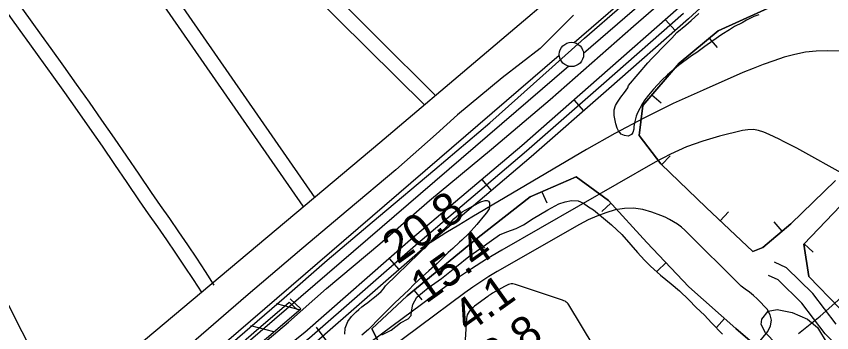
# Model space of a CAD drawing. Extents: x 3625074 to 3663148, y 511451 to 537151.
# Drawn here: x 3641799 to 3643476, y 523293 to 523944 of the extents above; entities that cross this region are included whole.
import ezdxf

# ---------------------------------------------------------------- set-up
doc = ezdxf.new("R2010")
doc.units = 0
for name, color, linetype in [('V-BORW-LINE', 7, 'Continuous'), ('V-FLOD-BASE', 7, 'Continuous'), ('V-LEVE-TOET', 7, 'Continuous'), ('V-RIVR-RANG', 7, 'Continuous'), ('V-ROAD-CNTR', 7, 'Continuous'), ('V-RRAP-FSHR', 7, 'Continuous'), ('V-SITE-VEGE', 7, 'Continuous'), ('V-SURV-LINE', 7, 'Continuous'), ('V-TOPO-DPTH', 7, 'Continuous'), ('V-TOPO-MINR', 7, 'Continuous'), ('V-TOPO-SHOR', 7, 'Continuous')]:
    doc.layers.add(name, color=color, linetype=linetype)

msp = doc.modelspace()

# ---------------------------------------------------------------- linework, layer by layer
at = {"layer": 'V-BORW-LINE'}
for p, q in [((3643224.4, 523898.9), (3643240.4, 523879.7)), ((3643106.3, 523782.3), (3643125.2, 523766)), ((3643126.5, 523638.8), (3643143.9, 523656.9)), ((3642880.2, 523583.2), (3642890.2, 523560.3)), ((3643022, 523559.4), (3643003.6, 523542.5)), ((3643246.8, 523523.6), (3643264, 523541.7)), ((3643374.1, 523502.3), (3643358, 523521.3)), ((3642745.8, 523486.1), (3642761.7, 523466.8)), ((3643419.6, 523476.2), (3643437.7, 523458.9)), ((3643135.4, 523437.3), (3643117.3, 523420)), ((3642617.1, 523380.3), (3642633, 523361)), ((3643255.8, 523322.3), (3643239.1, 523303.7))]:
    msp.add_line(p, q, dxfattribs=at)
for points in [[(3643484, 523606.3), (3643392, 523517.4), (3643334.4, 523468.5), (3643313.8, 523460.2), (3643218, 523550.8), (3643124.7, 523640.6), (3643080.3, 523698.5), (3643087.7, 523760.7), (3643162.2, 523847.3), (3643242.7, 523914.1), (3643381.8, 523977.8), (3643447.3, 523989.3), (3643529.5, 523993.4)], [(3643529.5, 523993.4), (3643447.3, 523989.3), (3643381.8, 523977.8), (3643242.7, 523914.1), (3643162.2, 523847.3), (3643087.7, 523760.7), (3643080.3, 523698.5), (3643124.7, 523640.6), (3643218, 523550.8), (3643313.8, 523460.2), (3643334.4, 523468.5), (3643392, 523517.4), (3643484, 523606.3)], [(3643375, 523158.9), (3643273.5, 523101.1), (3643205.5, 523058.5), (3643146.1, 523014.8), (3643079, 522959.4), (3643024.6, 522924.2), (3642958.5, 522908.3), (3642875.7, 522934.7), (3642769.3, 523010.4), (3642676.7, 523100.7), (3642574.7, 523212.8), (3642530.5, 523301.4), (3642603.3, 523368.9), (3642749, 523488.7), (3642856, 523572.7), (3642950.3, 523613.8), (3643016.9, 523565), (3643096.1, 523478.5), (3643182.6, 523387.8), (3643278.9, 523301.7), (3643371.1, 523222.8), (3643404.9, 523181.4), (3643398.8, 523171.9), (3643370.1, 523156.1)], [(3643370.1, 523156.1), (3643398.8, 523171.9), (3643404.9, 523181.4), (3643371.1, 523222.8), (3643278.9, 523301.7), (3643182.6, 523387.8), (3643096.1, 523478.5), (3643016.9, 523565), (3642950.3, 523613.8), (3642856, 523572.7), (3642749, 523488.7), (3642603.3, 523368.9), (3642530.5, 523301.4), (3642574.7, 523212.8), (3642676.7, 523100.7), (3642769.3, 523010.4), (3642875.7, 522934.7), (3642958.5, 522908.3), (3643024.6, 522924.2), (3643079, 522959.4), (3643146.1, 523014.8), (3643205.5, 523058.5), (3643273.5, 523101.1), (3643375, 523158.9)], [(3643491.5, 523344.1), (3643429.3, 523409), (3643418.7, 523475.3), (3643494.2, 523554.1)], [(3643494.2, 523554.1), (3643418.7, 523475.3), (3643429.3, 523409), (3643491.5, 523344.1)]]:
    msp.add_lwpolyline(points, dxfattribs=at)
at = {"layer": 'V-FLOD-BASE'}
msp.add_lwpolyline([(3640084.7, 521422.5), (3640206.5, 521525.7), (3640349.2, 521649.5), (3640530.1, 521801.4), (3640700.2, 521944.7), (3640815.3, 522042.4), (3640935.5, 522146.4), (3641004.7, 522203.9), (3641096.4, 522280.2), (3641207.3, 522373.9), (3641292.3, 522443.2), (3641395, 522533), (3641502.5, 522624.4), (3641618.4, 522721.2), (3641693.6, 522786.7), (3641777.8, 522856.7), (3641876.2, 522941), (3641962.2, 523015.9), (3642078.1, 523113.5), (3642175.7, 523196.2), (3642287.5, 523294), (3642360.1, 523356.2), (3642377.5, 523340.3)], dxfattribs=at)
at = {"layer": 'V-LEVE-TOET'}
for points in [[(3641773.7, 522787.8), (3641839.9, 522855.8), (3641920.2, 522930.4), (3641999.6, 523001.6), (3642112.5, 523101.3), (3642236.2, 523211.8), (3642358.8, 523315.2), (3642437.1, 523384.5), (3642546.6, 523476.2), (3642648.7, 523564.9), (3642776.2, 523670.5), (3642897.2, 523773.1), (3643068.6, 523923.3), (3643211.9, 524048.6), (3643296.8, 524120.9), (3643330.7, 524156.9), (3643348, 524170.9), (3643379.3, 524190.1), (3643409.3, 524208.5), (3643430.4, 524223.5), (3643456, 524241.7), (3643472.5, 524256.5), (3643504.8, 524290.1)], [(3642945.3, 523946.4), (3642876.6, 523877.7), (3642798.6, 523817.2), (3642706.5, 523741.1), (3642662.7, 523701.4), (3642579.5, 523628.2), (3642481.6, 523545.8), (3642386.1, 523465.8), (3642270.9, 523367.8), (3642158.8, 523270.6), (3642018.1, 523150.9), (3641911.7, 523056.7), (3641792.6, 522962)]]:
    msp.add_lwpolyline(points, dxfattribs=at)
at = {"layer": 'V-ROAD-CNTR'}
for p, q in [((3643153.9, 523914.3), (3643134.1, 523936.8)), ((3642966, 523749.3), (3642946.2, 523771.9)), ((3642776.7, 523585.7), (3642757.3, 523608.6)), ((3642586.7, 523423.5), (3642566.9, 523446.1))]:
    msp.add_line(p, q, dxfattribs=at)
for points in [[(3641531.3, 522821.3), (3641851.4, 523101.1), (3642546.6, 523684.6), (3643178.2, 524219.8), (3643515, 524516.6), (3644577.1, 525427.6), (3644649.7, 525493.9)], [(3641481.6, 524913.4), (3642413.1, 523570.8)], [(3641759.4, 522860.1), (3641937.2, 523010.9), (3642077.2, 523130.7), (3642213.8, 523247.3), (3642349.7, 523364.8), (3642438.7, 523442.6), (3642544.1, 523531.2), (3642660.1, 523629.1), (3642772.9, 523724.7), (3642901.5, 523839.2), (3642967.5, 523899.2), (3643044.9, 523966.1), (3643170.8, 524070.2), (3643269.5, 524151.7), (3643357.5, 524224.7), (3643379, 524244.2), (3643390, 524254), (3643408.6, 524270.7), (3643449.8, 524305.7), (3643542.1, 524386.6)], [(3641981, 524140.9), (3642388.4, 523553.7)], [(3643376.5, 524137.1), (3643310.1, 524056.4), (3643181.5, 523938.5), (3643017.7, 523794.7), (3642858.3, 523654.8), (3642629.7, 523461.2), (3642412, 523270.7), (3642307.5, 523187.5), (3642202.2, 523096.9), (3642137.4, 523040.9), (3642086.8, 522990.9), (3642054.2, 522948.8), (3642038.4, 522910.8), (3642039, 522889), (3642040.9, 522865), (3642051.8, 522825.6), (3642068.8, 522782.8), (3642084.3, 522721.3), (3642106.6, 522661.5), (3642134.3, 522618), (3642159.8, 522585), (3642187.5, 522517.2), (3642202.2, 522460.1), (3642207.9, 522380)], [(3642660.2, 523782.6), (3642422.8, 524018.5)], [(3642206.2, 523391.3), (3642188.3, 523418.9), (3642170.2, 523446.4), (3642151.9, 523473.8), (3642133.4, 523501), (3642114.7, 523528.1), (3642095.8, 523555.1), (3642076.8, 523581.8), (3642051.7, 523619), (3642026.4, 523656.3), (3642000.8, 523693.5), (3641975.1, 523730.6), (3641949.3, 523767.6), (3641923.2, 523804.4), (3641897, 523841.2), (3641870.7, 523877.8), (3641851, 523904.7), (3641831.6, 523931.7), (3641812.4, 523958.8), (3641781.7, 524003)], [(3642181.1, 523375), (3642163.2, 523402.5), (3642145.2, 523429.8), (3642127, 523457), (3642108.6, 523484.1), (3642090, 523511), (3642071.3, 523537.8), (3642052.2, 523564.7), (3642026.9, 523602.2), (3642001.6, 523639.4), (3641976.1, 523676.5), (3641950.5, 523713.5), (3641924.7, 523750.3), (3641898.8, 523787.1), (3641872.7, 523823.7), (3641846.4, 523860.2), (3641826.7, 523887.1), (3641807.2, 523914.3), (3641787.9, 523941.6), (3641756.9, 523986.1)], [(3642639.1, 523761.3), (3642401.7, 523997.2)], [(3643161.5, 523960.9), (3642997.9, 523817.2), (3642838.7, 523677.5), (3642610.1, 523483.9), (3642392.8, 523293.7), (3642288.4, 523210.6), (3642182.6, 523119.6), (3642117.1, 523063), (3642064.3, 523010.9), (3642028, 522964), (3642008.3, 522916.5), (3642009, 522887.4), (3642011.3, 522859.7), (3642023.3, 522816.1), (3642040.2, 522773.5), (3642055.6, 522712.3), (3642079.6, 522648.1), (3642109.8, 522600.8), (3642133.6, 522569.9), (3642159, 522507.7), (3642172.4, 522455.3), (3642176.7, 522394.7)], [(3643171.5, 523949.7), (3643007.8, 523805.9), (3642848.5, 523666.2), (3642619.9, 523472.6), (3642402.4, 523282.2), (3642298, 523199.1), (3642192.4, 523108.3), (3642127.3, 523052), (3642075.5, 523000.9), (3642041.1, 522956.4), (3642023.4, 522913.6), (3642024, 522888.2), (3642026.1, 522862.3), (3642037.5, 522820.9), (3642054.5, 522778.1), (3642070, 522716.8), (3642093.1, 522654.8), (3642122, 522609.4), (3642146.7, 522577.4), (3642173.3, 522512.4), (3642187.3, 522457.7), (3642193.4, 522371.6)], [(3641533.4, 523841), (3641893.6, 523132.1)], [(3643485, 523311), (3643437.2, 523373.6), (3643383.2, 523426.9), (3643358.6, 523438.2)], [(3643517.3, 523237), (3643462.4, 523291.1), (3643414.6, 523353.7), (3643365.9, 523401.8), (3643346.1, 523410.9)], [(3642415.6, 523304.8), (3642443.4, 523267.9), (3642466.5, 523241.1), (3642485.7, 523217.2), (3642519.6, 523179.9), (3642562.5, 523130.5), (3642612, 523072.4), (3642677.6, 523002.7), (3642726.4, 522957.6), (3642774, 522925.7), (3642830.3, 522901.3), (3642884.4, 522883.9), (3642942.1, 522880.4), (3642983.3, 522886.7), (3643078.4, 522923.2), (3643173, 522979.4), (3643261.4, 523030.7), (3643325.6, 523069.4), (3643362.4, 523096.7), (3643389.7, 523114.2), (3643407.6, 523140.2), (3643411.9, 523159.7)]]:
    msp.add_lwpolyline(points, dxfattribs=at)
at = {"layer": 'V-RRAP-FSHR'}
for p, q in [((3642381.7, 523340.6), (3642334.4, 523352.9)), ((3642328.4, 523295.2), (3642281.1, 523307.4))]:
    msp.add_line(p, q, dxfattribs=at)
msp.add_lwpolyline([(3641583.2, 522658.8), (3642384.1, 523342.7), (3642362.2, 523362.9)], dxfattribs=at)
at = {"layer": 'V-SITE-VEGE'}
for points in [[(3643326.4, 523947), (3643316.1, 523943.3), (3643301.2, 523935.9), (3643291.9, 523930.6), (3643276.3, 523922.6), (3643265.7, 523916.3), (3643250, 523906.3), (3643243.4, 523901.9), (3643215, 523881.5), (3643198.7, 523869.5), (3643187.7, 523862.3), (3643161, 523842.8), (3643138.5, 523823.5), (3643127.1, 523812.7), (3643109.9, 523794.3), (3643099.1, 523781.5), (3643092, 523772.2), (3643086.8, 523764.8), (3643076.8, 523745.2), (3643074.3, 523738.7), (3643071.8, 523730.3), (3643070.7, 523724.8), (3643069.5, 523717), (3643069, 523711.7), (3643066.8, 523704.9), (3643064.4, 523700.8), (3643057.5, 523697.7), (3643049.7, 523698.6), (3643043.2, 523701.4), (3643037.8, 523708.1), (3643035.1, 523713.7), (3643032, 523722.9), (3643030.6, 523729.8), (3643028.9, 523740), (3643028.8, 523746.6), (3643028.9, 523751.8), (3643031.8, 523760.5), (3643035.9, 523767.3), (3643042.4, 523777.5), (3643049.9, 523787.1), (3643057, 523796.7), (3643058.5, 523801.3), (3643098, 523847.9), (3643106.1, 523857.1), (3643114.9, 523865.7), (3643127.7, 523878.7), (3643147.2, 523899.1), (3643157.7, 523910.2), (3643176.1, 523925.4), (3643187.1, 523935.2), (3643203.2, 523949.8)], [(3642474.6, 523290.6), (3642475.6, 523302.4), (3642478, 523309.2), (3642480.9, 523316.3), (3642488.7, 523326.8), (3642497.8, 523336.4), (3642503.8, 523341.1), (3642509.8, 523346.2), (3642515.5, 523350.6), (3642522.2, 523355.3), (3642526.2, 523358.5), (3642533.2, 523364.5), (3642539.2, 523369.2), (3642549.3, 523377.7), (3642554.4, 523383.8), (3642558.4, 523389.6), (3642627.4, 523456.9), (3642636.4, 523465.5), (3642639.8, 523468), (3642647.8, 523476.3), (3642652.5, 523480.7), (3642658.6, 523488.4), (3642663.4, 523493.5), (3642673.1, 523501.4), (3642680.4, 523507.7), (3642691.9, 523519.5), (3642699, 523527.1), (3642709, 523536.3), (3642716.1, 523541.7), (3642738.6, 523554.4), (3642754.6, 523562.5), (3642763.5, 523564.8), (3642767.7, 523565.4), (3642770.3, 523563.7), (3642772.1, 523560), (3642772.3, 523553.1), (3642771.5, 523547.9), (3642766.3, 523539.9), (3642762.3, 523534.8), (3642746.4, 523516), (3642728.8, 523496.5), (3642715.7, 523483.5), (3642710.7, 523479.1), (3642696.6, 523466.1), (3642687.5, 523458.1), (3642674.1, 523445.5), (3642664.7, 523435.9), (3642647.6, 523420.4), (3642634.8, 523409), (3642617, 523392.2), (3642606.3, 523381.3), (3642577.7, 523354.4), (3642561.9, 523339.1), (3642552.8, 523329.9), (3642539.7, 523316.9), (3642531.6, 523308), (3642523.5, 523300), (3642509.8, 523288.3)]]:
    msp.add_lwpolyline(points, dxfattribs=at)
msp.add_lwpolyline([(3643430, 523200.7), (3643340.1, 523293), (3643330.8, 523310), (3643332.5, 523321.2), (3643345.6, 523337.6), (3643363.9, 523341.3), (3643394.6, 523334.9), (3643426.4, 523321.3), (3643446.9, 523303.9), (3643467, 523271.2), (3643476.1, 523244.3), (3643471.1, 523219.2), (3643463.9, 523209.6)], close=True, dxfattribs=at)
at = {"layer": 'V-SURV-LINE'}
for points in [[(3642946.2, 523889.8), (3644885, 525562.9)], [(3644904.6, 525540.2), (3642965.8, 523867.1)], [(3641453.3, 522606.6), (3642915.9, 523863.7)], [(3642935.5, 523841), (3641472.8, 522583.8)]]:
    msp.add_lwpolyline(points, dxfattribs=at)
msp.add_circle((3642940.9, 523865.4), 25, dxfattribs=at)
at = {"layer": 'V-TOPO-DPTH'}
for points in [[(3643352.4, 523318.9), (3643349.6, 523330.2), (3643343.5, 523341.5), (3643337.4, 523348.2), (3643330.3, 523355.7), (3643322.8, 523363), (3643315, 523369.8), (3643306.9, 523376.3), (3643298.5, 523382.5), (3643290.1, 523388.7), (3643174.1, 523504.2), (3643166.9, 523510.6), (3643159.1, 523516.4), (3643150.9, 523521.5), (3643142.4, 523526.3), (3643133.6, 523530.5), (3643124.6, 523534.3), (3643106, 523541.4), (3643087.4, 523546.6), (3643068.7, 523549.4), (3643049.8, 523548.7), (3643030.8, 523545.7), (3643030.5, 523545.6), (3643011.5, 523539.9), (3642993, 523533.2), (3642975, 523525.1), (3642957.4, 523515.9), (3642788.1, 523418.8), (3642771.1, 523408.6), (3642754.3, 523398), (3642737.9, 523386.8), (3642721.7, 523375.3), (3642533.8, 523235.7)], [(3643322, 523268.1), (3643344.6, 523296), (3643350.2, 523307.5), (3643352.4, 523318.9)]]:
    msp.add_lwpolyline(points, dxfattribs=at)
at = {"layer": 'V-TOPO-MINR'}
for points in [[(3643550.9, 523872.2), (3643466.9, 523873), (3643444.4, 523872.1), (3643422.1, 523869.9), (3643400.1, 523865.5), (3643378.3, 523859.8), (3643356.8, 523852.6), (3643335.5, 523845), (3643314.4, 523836.7), (3643293.5, 523828), (3643211.5, 523792.2), (3643150.2, 523764.2), (3643089.8, 523734.6), (3643030.4, 523702.9), (3642971.8, 523669.8), (3642735.9, 523530.6), (3642709.1, 523514.6), (3642682.3, 523498.3), (3642655.7, 523481.8), (3642630.1, 523465.6)], [(3643611.5, 523557.3), (3643404.5, 523672.7), (3643378.6, 523685.7), (3643368.2, 523690.9), (3643357.7, 523695.9), (3643347.2, 523700.7), (3643336.6, 523705.5), (3643325.8, 523708.9), (3643315, 523710.9), (3643303.9, 523710.7), (3643292.8, 523709.1), (3643245.4, 523697.4), (3643211, 523687.3), (3643177.4, 523675.3), (3643144.8, 523660.7), (3643113, 523644.1), (3642797.8, 523463.2), (3642766.2, 523444.4), (3642735, 523424.7), (3642704.6, 523404), (3642674.7, 523382.6), (3642322, 523120.7)], [(3643352.4, 523318.9), (3643349.6, 523330.2), (3643343.5, 523341.5), (3643337.4, 523348.2), (3643330.3, 523355.7), (3643322.8, 523363), (3643315, 523369.8), (3643306.9, 523376.3), (3643298.5, 523382.5), (3643290.1, 523388.7), (3643174.1, 523504.2), (3643166.9, 523510.6), (3643159.1, 523516.4), (3643150.9, 523521.5), (3643142.4, 523526.3), (3643133.6, 523530.5), (3643124.6, 523534.3), (3643106, 523541.4), (3643087.4, 523546.6), (3643068.7, 523549.4), (3643049.8, 523548.7), (3643030.8, 523545.7), (3643030.5, 523545.6), (3643011.5, 523539.9), (3642993, 523533.2), (3642975, 523525.1), (3642957.4, 523515.9), (3642788.1, 523418.8), (3642771.1, 523408.6), (3642754.3, 523398), (3642737.9, 523386.8), (3642721.7, 523375.3), (3642533.8, 523235.7)], [(3643037.3, 523181.2), (3642935.8, 523350.5), (3642934.1, 523352.7), (3642932.2, 523354.7), (3642930, 523356.4), (3642927.7, 523357.9), (3642925.2, 523359.1), (3642922.6, 523360.2), (3642825.7, 523392.7), (3642822.8, 523393.3), (3642820, 523393.7), (3642817.1, 523393.5), (3642814.2, 523393), (3642811.3, 523392.1), (3642808.6, 523391.1), (3642805.9, 523389.9), (3642803.2, 523388.5), (3642778.5, 523374.3), (3642776, 523372.8), (3642773.5, 523371.3), (3642771.1, 523369.6), (3642768.7, 523367.9), (3642741.6, 523347.7), (3642738.5, 523345.3), (3642735.6, 523342.6), (3642732.8, 523339.8), (3642730.3, 523336.8), (3642728.1, 523333.6), (3642726.5, 523330.2), (3642725.4, 523326.6), (3642724.8, 523322.7), (3642718.9, 523225.4)], [(3643407.6, 523291.5), (3643452.4, 523327.1), (3643495, 523365)], [(3643322, 523268.1), (3643344.6, 523296), (3643350.2, 523307.5), (3643352.4, 523318.9)]]:
    msp.add_lwpolyline(points, dxfattribs=at)
at = {"layer": 'V-TOPO-SHOR'}
for points in [[(3642550.6, 523288.6), (3642569.9, 523298.5), (3642589.1, 523313.7), (3642605.1, 523321.6), (3642611.4, 523328.6), (3642612, 523336.6), (3642614.8, 523351.3), (3642623.2, 523366.3), (3642646, 523385.7), (3642673.4, 523404.8), (3642704.5, 523429.6), (3642729.7, 523449.7), (3642754.6, 523466.9), (3642776.2, 523482.9), (3642793, 523494.2), (3642808, 523501), (3642827.4, 523507.2), (3642842.4, 523515.2), (3642862.1, 523527.9), (3642892.1, 523546.2), (3642914.7, 523558.4), (3642927.8, 523562.4), (3642940.8, 523565.3), (3642954.7, 523564.7), (3642965.6, 523559.5), (3642975.8, 523552.3), (3642986.5, 523546.2)], [(3642986.5, 523546.2), (3643023.3, 523514.8), (3643044.6, 523495.2), (3643063.1, 523473.9), (3643077, 523458.1), (3643091, 523442.7), (3643103.3, 523430.1), (3643123.8, 523411.6), (3643145.9, 523393.6), (3643163.2, 523379.4), (3643182.6, 523360.9), (3643197.5, 523344.9), (3643214.2, 523329.1), (3643228.8, 523313.5), (3643251.3, 523290.1)]]:
    msp.add_lwpolyline(points, dxfattribs=at)

# ---------------------------------------------------------------- texts
at = {"layer": 'V-RIVR-RANG'}
for s, p in [('20.8', (3642583.1, 523432.9)), ('15.4', (3642641.4, 523351.7)), ('4.1', (3642728.7, 523291.1)), ('2.8', (3642785.1, 523208.5))]:
    msp.add_text(s, height=67, rotation=35.5283, dxfattribs=at).set_placement(p)

doc.saveas('drawing.dxf')
